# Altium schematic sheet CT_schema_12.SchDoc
size 278 x 170 mm
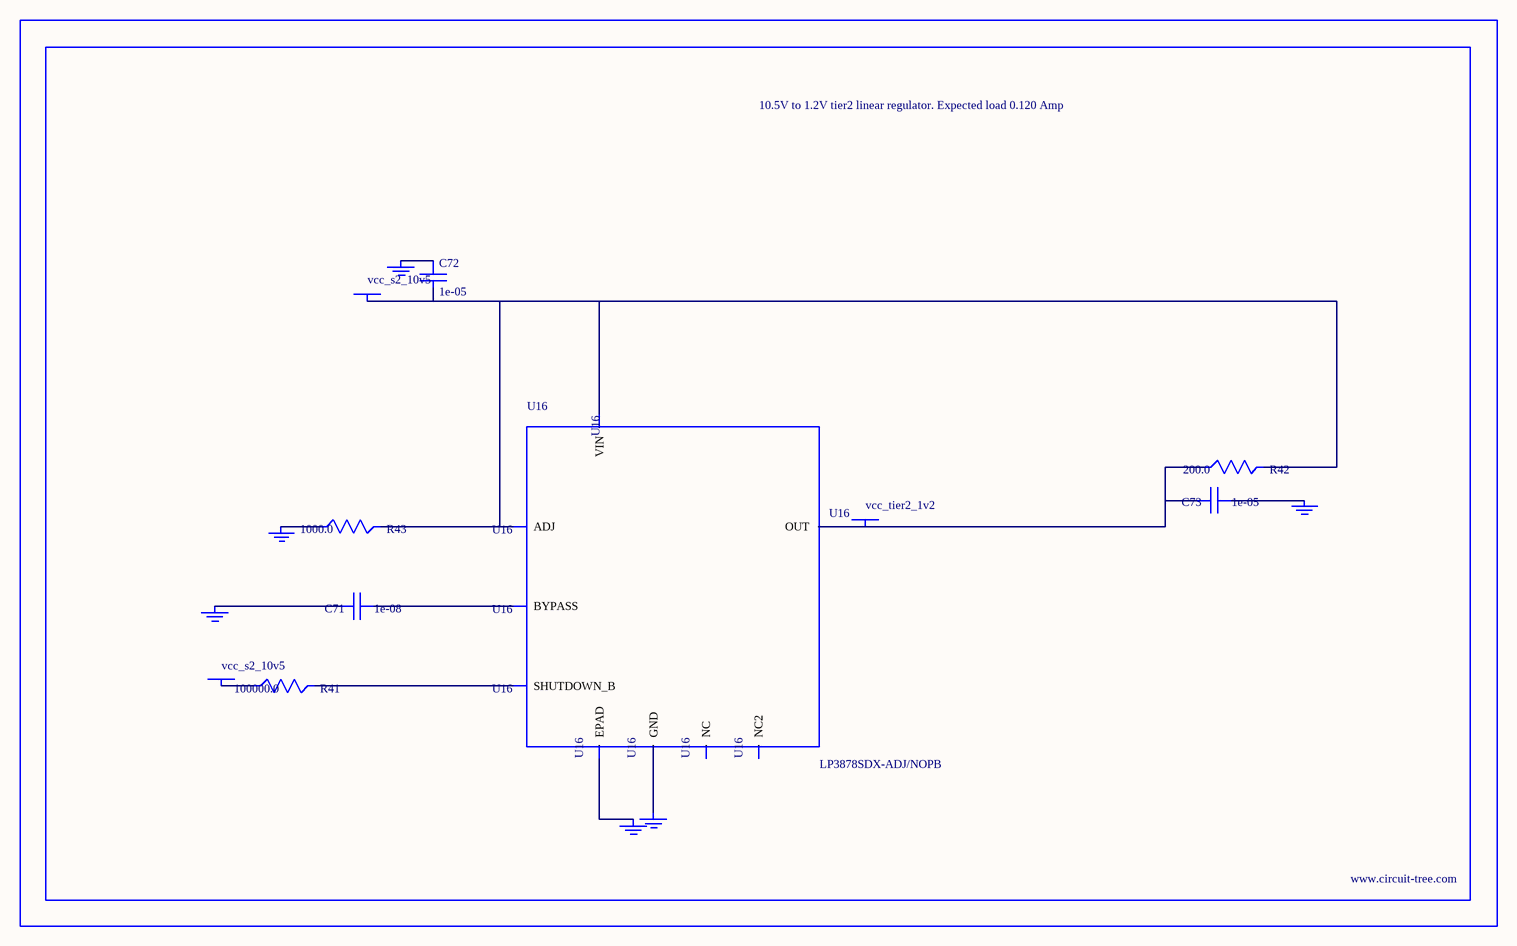
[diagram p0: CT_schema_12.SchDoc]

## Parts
BORDER11  (no value)
C71  1e-08  [C0402]
C72  1e-05  [C1206]
C73  1e-05  [C0805]
GND_INSTANCE_11_0  (no value)
GND_INSTANCE_11_1  (no value)
GND_INSTANCE_11_2  (no value)
GND_INSTANCE_11_3  (no value)
GND_INSTANCE_11_4  (no value)
GND_INSTANCE_11_5  (no value)
POWER_INSTANCE_11_0  vcc_s2_10v5
POWER_INSTANCE_11_1  vcc_s2_10v5
POWER_INSTANCE_11_2  vcc_tier2_1v2
R41  100000.0  [R0603]
R42  200.0  [R0603]
R43  1000.0  [R0603]
U16  LP3878SDX-ADJ/NOPB  [WSON-8]

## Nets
NetC71_1: C71.1 U16.1(BYPASS)
NetC71_2: C71.2 GND_INSTANCE_11_0.0(GND)
NetC72_1: C72.1 GND_INSTANCE_11_1.0(GND)
NetC72_2: C72.2 POWER_INSTANCE_11_0.0(PWR) R42.2 R43.2 U16.4(VIN) U16.6(ADJ)
NetC73_1: C73.1 GND_INSTANCE_11_2.0(GND)
NetC73_2: C73.2 POWER_INSTANCE_11_2.0(PWR) R42.1 U16.5(OUT)
NetGND_INSTANCE_11_3_0: GND_INSTANCE_11_3.0(GND) R43.1
NetGND_INSTANCE_11_4_0: GND_INSTANCE_11_4.0(GND) U16.PAD(EPAD)
NetGND_INSTANCE_11_5_0: GND_INSTANCE_11_5.0(GND) U16.3(GND)
NetPOWER_INSTANCE_11_1_0: POWER_INSTANCE_11_1.0(PWR) R41.1
NetR41_2: R41.2 U16.8(SHUTDOWN_B)

Not connected (* = marked no-connect by the designer): U16 2(NC) 7(NC2)

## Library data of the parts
BORDER11 = BORDER_PAGE11
C71 = C0402C103K3RAC
C72 = C1206C106K3RACTU
C73 = GRM219R60J106ME19D
GND_INSTANCE_11_0-GND_INSTANCE_11_5 = GND
POWER_INSTANCE_11_0-POWER_INSTANCE_11_2 = PWR
R41 = RC0603JR-07100KL
R42 = RC0603JR-07200RL
R43 = RC0603JR-071KL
